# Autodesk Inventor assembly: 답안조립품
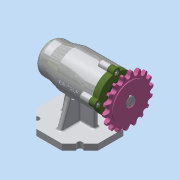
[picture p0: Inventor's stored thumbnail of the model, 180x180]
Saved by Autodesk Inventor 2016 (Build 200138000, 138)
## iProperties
Created: 2021-01
Part Number: 답안조립품
Material: 일반
Document SubType Name: Assembly
Designer: Administrator
Author: Administrator
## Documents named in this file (12)
- C:\Users\Administrator\Desktop\710106V1038\답안조립품.iam
- C:\Users\Administrator\Desktop\710106V1038\본체.ipt
- C:\Users\Administrator\Desktop\710106V1038\베어링 6004.ipt
- C:\Users\Administrator\Desktop\710106V1038\축.ipt
- C:\Users\Administrator\Desktop\710106V1038\어댑터슬리브.ipt
- C:\Users\Administrator\Desktop\710106V1038\볼트 M4.ipt
- C:\Users\Administrator\Desktop\710106V1038\베어링 51202.ipt
- C:\Users\Administrator\Desktop\710106V1038\커버.ipt
- C:\Users\Administrator\Desktop\710106V1038\오일 실.ipt
- C:\Users\Administrator\Desktop\710106V1038\키 5 x 5 x 14.ipt
- C:\Users\Administrator\Desktop\710106V1038\스프로킷.ipt
- C:\Users\Administrator\Desktop\710106V1038\멈춤나사 M3.ipt
